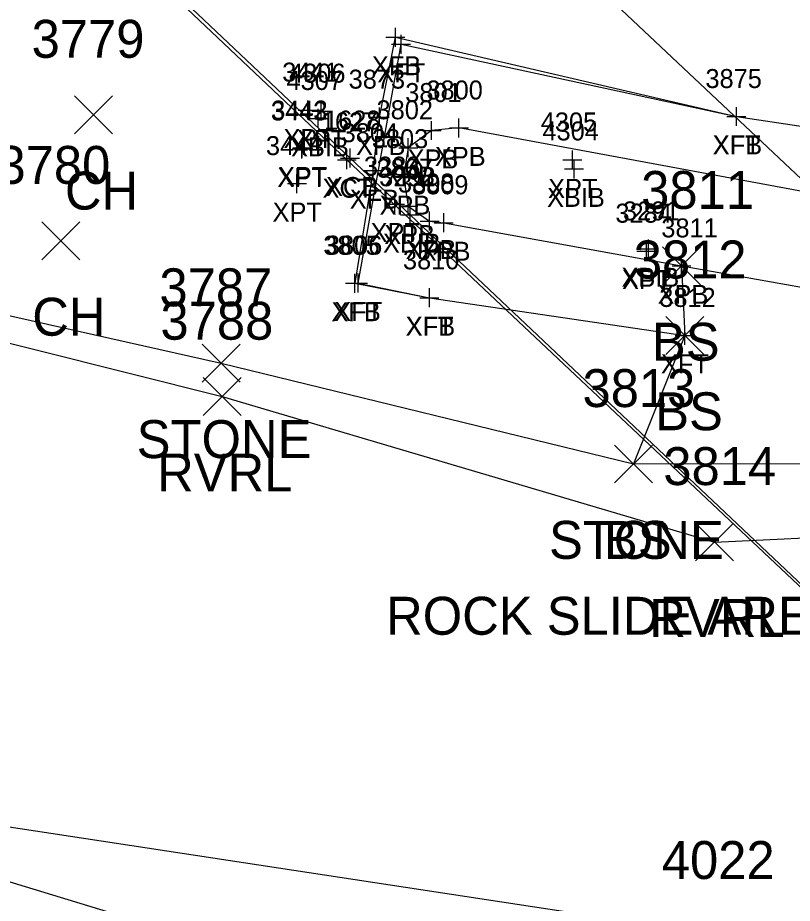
# Model space of a CAD drawing. Extents: x 1647574 to 1652703, y 212895 to 228670.
# Drawn here: x 1648950.84 to 1648991.67, y 227169.71 to 227216.38 of the extents above; entities that cross this region are included whole.
import ezdxf

# ---------------------------------------------------------------- set-up
doc = ezdxf.new("R2010")
doc.units = 0
for name, color, linetype in [('B_A', 7, 'Continuous'), ('B_I', 7, 'Continuous'), ('B_TIC', 7, 'Continuous'), ('BDC', 7, 'Continuous'), ('BELB', 7, 'Continuous'), ('BFT', 7, 'Continuous'), ('BSUBM', 7, 'Continuous'), ('L_A', 7, 'Continuous'), ('L_C', 7, 'Continuous'), ('L_I', 7, 'Continuous'), ('L_TIC', 7, 'Continuous'), ('LASF', 7, 'Continuous'), ('LAWE', 7, 'Continuous'), ('LELB', 7, 'Continuous')]:
    doc.layers.add(name, color=color, linetype=linetype)

msp = doc.modelspace()

# ---------------------------------------------------------------- linework, layer by layer
at = {"layer": 'B_TIC'}
for p, q in [((1648970.75, 227215.354), (1648970.825, 227215.354)), ((1648971.054, 227214.981), (1648971.129, 227214.981)), ((1648966.13, 227211.517), (1648966.205, 227211.517)), ((1648966.678, 227211.075), (1648966.754, 227211.075)), ((1648966.843, 227211.462), (1648966.918, 227211.462)), ((1648969.916, 227211.146), (1648969.991, 227211.146)), ((1648988.726, 227211.177), (1648988.801, 227211.177)), ((1648988.726, 227211.177), (1648988.801, 227211.177)), ((1648974.097, 227210.575), (1648974.172, 227210.575)), ((1648972.655, 227210.44), (1648972.73, 227210.44)), ((1648965.814, 227209.469), (1648965.889, 227209.469)), ((1648965.838, 227209.518), (1648965.913, 227209.518)), ((1648971.426, 227209.531), (1648971.502, 227209.531)), ((1648968.19, 227208.898), (1648968.265, 227208.898)), ((1648968.358, 227208.988), (1648968.434, 227208.988)), ((1648980.081, 227208.89), (1648980.157, 227208.89)), ((1648969.587, 227208.323), (1648969.662, 227208.323)), ((1648969.587, 227208.323), (1648969.662, 227208.323)), ((1648980.172, 227208.415), (1648980.248, 227208.415)), ((1648971.178, 227208.007), (1648971.254, 227208.007)), ((1648965.555, 227207.643), (1648965.631, 227207.643)), ((1648970.722, 227206.561), (1648970.798, 227206.561)), ((1648971.428, 227206.454), (1648971.503, 227206.454)), ((1648971.523, 227206.001), (1648971.599, 227206.001)), ((1648972.555, 227205.669), (1648972.63, 227205.669)), ((1648973.298, 227205.577), (1648973.374, 227205.577)), ((1648983.98, 227204.082), (1648984.055, 227204.082)), ((1648984.095, 227204.202), (1648984.17, 227204.202)), ((1648985.833, 227203.305), (1648985.909, 227203.305)), ((1648968.618, 227202.39), (1648968.694, 227202.39)), ((1648968.782, 227202.399), (1648968.858, 227202.399)), ((1648968.782, 227202.399), (1648968.858, 227202.399)), ((1648972.54, 227201.623), (1648972.615, 227201.623)), ((1648972.54, 227201.623), (1648972.615, 227201.623)), ((1648986.007, 227199.641), (1648986.082, 227199.641))]:
    msp.add_line(p, q, dxfattribs=at)
for points in [[(1648970.746, 227214.854), (1648970.746, 227215.854)], [(1648970.246, 227215.354), (1648971.246, 227215.354)], [(1648971.05, 227214.481), (1648971.05, 227215.481)], [(1648970.55, 227214.981), (1648971.55, 227214.981)], [(1648966.126, 227211.017), (1648966.126, 227212.017)], [(1648965.626, 227211.517), (1648966.626, 227211.517)], [(1648966.675, 227210.575), (1648966.675, 227211.575)], [(1648966.839, 227210.962), (1648966.839, 227211.962)], [(1648969.912, 227210.646), (1648969.912, 227211.646)], [(1648988.722, 227210.677), (1648988.722, 227211.677)], [(1648988.722, 227210.677), (1648988.722, 227211.677)], [(1648966.175, 227211.075), (1648967.175, 227211.075)], [(1648966.339, 227211.462), (1648967.339, 227211.462)], [(1648969.412, 227211.146), (1648970.412, 227211.146)], [(1648974.093, 227210.075), (1648974.093, 227211.075)], [(1648988.222, 227211.177), (1648989.222, 227211.177)], [(1648988.222, 227211.177), (1648989.222, 227211.177)], [(1648972.651, 227209.94), (1648972.651, 227210.94)], [(1648973.593, 227210.575), (1648974.593, 227210.575)], [(1648972.151, 227210.44), (1648973.151, 227210.44)], [(1648965.81, 227208.969), (1648965.81, 227209.969)], [(1648965.834, 227209.018), (1648965.834, 227210.018)], [(1648971.423, 227209.031), (1648971.423, 227210.031)], [(1648965.31, 227209.469), (1648966.31, 227209.469)], [(1648965.334, 227209.518), (1648966.334, 227209.518)], [(1648968.186, 227208.398), (1648968.186, 227209.398)], [(1648968.355, 227208.488), (1648968.355, 227209.488)], [(1648970.923, 227209.531), (1648971.923, 227209.531)], [(1648980.078, 227208.39), (1648980.078, 227209.39)], [(1648967.686, 227208.898), (1648968.686, 227208.898)], [(1648967.855, 227208.988), (1648968.855, 227208.988)], [(1648969.583, 227207.823), (1648969.583, 227208.823)], [(1648969.583, 227207.823), (1648969.583, 227208.823)], [(1648979.578, 227208.89), (1648980.578, 227208.89)], [(1648980.169, 227207.915), (1648980.169, 227208.915)], [(1648969.083, 227208.323), (1648970.083, 227208.323)], [(1648969.083, 227208.323), (1648970.083, 227208.323)], [(1648971.175, 227207.507), (1648971.175, 227208.507)], [(1648979.669, 227208.415), (1648980.669, 227208.415)], [(1648965.552, 227207.143), (1648965.552, 227208.143)], [(1648970.675, 227208.007), (1648971.675, 227208.007)], [(1648965.052, 227207.643), (1648966.052, 227207.643)], [(1648970.719, 227206.061), (1648970.719, 227207.061)], [(1648971.424, 227205.954), (1648971.424, 227206.954)], [(1648970.219, 227206.561), (1648971.219, 227206.561)], [(1648970.924, 227206.454), (1648971.924, 227206.454)], [(1648971.52, 227205.501), (1648971.52, 227206.501)], [(1648971.02, 227206.001), (1648972.02, 227206.001)], [(1648972.551, 227205.169), (1648972.551, 227206.169)], [(1648973.295, 227205.077), (1648973.295, 227206.077)], [(1648972.051, 227205.669), (1648973.051, 227205.669)], [(1648972.795, 227205.577), (1648973.795, 227205.577)], [(1648983.976, 227203.582), (1648983.976, 227204.582)], [(1648984.091, 227203.702), (1648984.091, 227204.702)], [(1648983.476, 227204.082), (1648984.476, 227204.082)], [(1648983.591, 227204.202), (1648984.591, 227204.202)], [(1648985.83, 227202.805), (1648985.83, 227203.805)], [(1648985.33, 227203.305), (1648986.33, 227203.305)], [(1648968.615, 227201.89), (1648968.615, 227202.89)], [(1648968.779, 227201.899), (1648968.779, 227202.899)], [(1648968.779, 227201.899), (1648968.779, 227202.899)], [(1648968.115, 227202.39), (1648969.115, 227202.39)], [(1648968.279, 227202.399), (1648969.279, 227202.399)], [(1648968.279, 227202.399), (1648969.279, 227202.399)], [(1648972.536, 227201.123), (1648972.536, 227202.123)], [(1648972.536, 227201.123), (1648972.536, 227202.123)], [(1648972.036, 227201.623), (1648973.036, 227201.623)], [(1648972.036, 227201.623), (1648973.036, 227201.623)], [(1648986.003, 227199.141), (1648986.003, 227200.141)], [(1648985.503, 227199.641), (1648986.503, 227199.641)]]:
    msp.add_lwpolyline(points, dxfattribs=at)
at = {"layer": 'BDC'}
for points in [[(1649190.777, 226999.084), (1649140.468, 227046.558), (1649090.33, 227093.733), (1649025.71, 227154.751), (1648968.186, 227208.898), (1648910.789, 227263.155), (1648860.431, 227310.794), (1648808.664, 227359.741)], [(1649190.944, 226999.114), (1649140.59, 227046.719), (1649090.397, 227093.864), (1649025.741, 227154.791), (1648968.355, 227208.988), (1648910.836, 227263.351), (1648860.59, 227310.809), (1648808.767, 227359.651)]]:
    msp.add_lwpolyline(points, dxfattribs=at)
at = {"layer": 'BELB'}
msp.add_lwpolyline([(1649218.046, 226994.506), (1649168.124, 227041.655), (1649117.675, 227088.79), (1649053.801, 227149.566), (1648996.598, 227203.697), (1648938.733, 227258.119), (1648889.571, 227305.276), (1648838.072, 227353.54)], dxfattribs=at)
at = {"layer": 'BFT'}
for points in [[(1648969.583, 227208.323), (1648969.912, 227211.146), (1648970.746, 227215.354), (1648988.722, 227211.177)], [(1648968.779, 227202.399), (1648971.05, 227214.981), (1648988.722, 227211.177), (1649022.914, 227206.066)], [(1648969.583, 227208.323), (1648968.615, 227202.39), (1648972.536, 227201.623)], [(1648968.779, 227202.399), (1648972.536, 227201.623), (1648986.003, 227199.641)]]:
    msp.add_lwpolyline(points, dxfattribs=at)
at = {"layer": 'BSUBM'}
msp.add_lwpolyline([(1648974.093, 227210.575), (1648972.651, 227210.44), (1648971.423, 227209.531), (1648971.175, 227208.007), (1648971.424, 227206.454), (1648972.551, 227205.669), (1648973.295, 227205.577), (1648985.83, 227203.305), (1648994.526, 227201.766), (1648998.617, 227201.072), (1649002.003, 227200.334), (1649005.371, 227199.79), (1649006.714, 227199.334), (1649014.364, 227197.781), (1649016.938, 227197.386), (1649018.515, 227197.402), (1649019.628, 227198.236), (1649020.065, 227199.413), (1649019.938, 227200.493), (1649019.383, 227201.576), (1649018, 227202.346), (1648995.997, 227206.525), (1648974.093, 227210.575)], dxfattribs=at)
at = {"layer": 'L_TIC'}
for points in [[(1648953.836, 227210.271), (1648955.836, 227212.271)], [(1648955.836, 227210.271), (1648953.836, 227212.271)], [(1648952.113, 227203.625), (1648954.113, 227205.625)], [(1648954.113, 227203.625), (1648952.113, 227205.625)], [(1648984.83, 227202.305), (1648986.83, 227204.305)], [(1648986.83, 227202.305), (1648984.83, 227204.305)], [(1648985.003, 227198.641), (1648987.003, 227200.641)], [(1648987.003, 227198.641), (1648985.003, 227200.641)], [(1648960.566, 227197.174), (1648962.566, 227199.174)], [(1648962.566, 227197.174), (1648960.566, 227199.174)], [(1648960.62, 227195.414), (1648962.62, 227197.414)], [(1648962.62, 227195.414), (1648960.62, 227197.414)], [(1648982.303, 227191.864), (1648984.303, 227193.864)], [(1648984.303, 227191.864), (1648982.303, 227193.864)], [(1648982.303, 227191.864), (1648984.303, 227193.864)], [(1648984.303, 227191.864), (1648982.303, 227193.864)], [(1648986.564, 227187.752), (1648988.564, 227189.752)], [(1648988.564, 227187.752), (1648986.564, 227189.752)]]:
    msp.add_lwpolyline(points, dxfattribs=at)
at = {"layer": 'LASF'}
for points in [[(1648499.797, 227390.788), (1648534.237, 227361.964), (1648564.139, 227335.998), (1648594.151, 227310.22), (1648628.599, 227293.401), (1648654.269, 227279.63), (1648686.156, 227265.624), (1648717.135, 227256.764), (1648740.627, 227248.949), (1648765.894, 227244.077), (1648814.223, 227231.854), (1648833.279, 227225.74), (1648856.547, 227221.689), (1648882.063, 227215.369), (1648909.355, 227210.97), (1648936.503, 227203.804), (1648961.566, 227198.174), (1648983.303, 227192.864), (1648997.705, 227192.889), (1649002.003, 227200.334)], [(1648591.009, 227270.343), (1648624.693, 227258.455), (1648664.933, 227242.862), (1648702.926, 227233.816), (1648737.154, 227219.4), (1648772.089, 227211.83), (1648798.883, 227202.714), (1648829.377, 227195.595), (1648870.643, 227189.301), (1648888.064, 227189.998), (1648910.238, 227184.26), (1648945.065, 227174.552), (1648988.129, 227167.991), (1649019.013, 227162.278), (1649093.93, 227148.389), (1649131.468, 227140.127), (1649155.823, 227137.226), (1649206.951, 227127.276), (1649258.232, 227116.863), (1649289.141, 227114.771), (1649313.58, 227109.451)]]:
    msp.add_lwpolyline(points, dxfattribs=at)
at = {"layer": 'LAWE'}
msp.add_lwpolyline([(1648882.174, 227213.58), (1648908.492, 227208.957), (1648937.017, 227202.591), (1648961.62, 227196.414), (1648987.564, 227188.752), (1648995.627, 227189.125), (1648999.847, 227187.562), (1649015.768, 227185.251), (1649058.819, 227180.733), (1649088.746, 227176.451), (1649126.054, 227169.003), (1649155.538, 227162.793), (1649190.065, 227156.482), (1649213.142, 227152.135), (1649245.722, 227144.443), (1649279.437, 227140.081), (1649297.816, 227135.47), (1649313.399, 227135.549)], dxfattribs=at)
at = {"layer": 'LELB'}
for points in [[(1648597.273, 227264.486), (1648633.73, 227250.634), (1648664.389, 227240.318), (1648701.872, 227228.729), (1648735.461, 227216.545), (1648770.192, 227206.754), (1648796.996, 227200.241), (1648829.006, 227192.504), (1648869.112, 227184.885), (1648887.117, 227184.175), (1648909.076, 227180.513), (1648944.404, 227172.664), (1648985.415, 227160.185), (1649015.972, 227155.751), (1649030.56, 227151.792), (1649075.874, 227142.707), (1649094.964, 227142.334), (1649128.793, 227137.178), (1649163.599, 227126.992), (1649206.12, 227120.023), (1649254.696, 227110.714), (1649288.497, 227104.847), (1649312.044, 227099.384)], [(1648985.83, 227203.305), (1648986.003, 227199.641), (1648983.303, 227192.864)]]:
    msp.add_lwpolyline(points, dxfattribs=at)

# ---------------------------------------------------------------- texts
at = {"layer": 'B_A'}
for s, p in [('XFB', (1648969.506, 227213.354)), ('XFT', (1648969.794, 227212.981)), ('XPT', (1648964.847, 227209.517)), ('XPT', (1648965.56, 227209.462)), ('XFB', (1648968.672, 227209.146)), ('XFT', (1648987.466, 227209.177)), ('XFB', (1648987.482, 227209.177)), ('XBIB', (1648965.246, 227209.075)), ('XPB', (1648971.388, 227208.44)), ('XPB', (1648972.829, 227208.575)), ('XPT', (1648964.531, 227207.469)), ('XPT', (1648964.555, 227207.518)), ('XPB', (1648970.159, 227207.531)), ('XCT', (1648966.907, 227206.898)), ('XCB', (1648967.091, 227206.988)), ('XPT', (1648978.798, 227206.89)), ('XFB', (1648968.343, 227206.323)), ('XFB', (1648968.343, 227206.323)), ('XBIB', (1648978.74, 227206.415)), ('XPB', (1648969.911, 227206.007)), ('XPT', (1648964.272, 227205.643)), ('XPT', (1648969.44, 227204.561)), ('XPB', (1648970.161, 227204.454)), ('XBIB', (1648970.091, 227204.001)), ('XPB', (1648971.288, 227203.669)), ('XPB', (1648972.031, 227203.577)), ('XBIB', (1648982.662, 227202.202)), ('XPT', (1648982.697, 227202.082)), ('XPB', (1648984.566, 227201.305)), ('XFB', (1648967.375, 227200.39)), ('XFT', (1648967.523, 227200.399)), ('XFT', (1648967.523, 227200.399)), ('XFT', (1648971.28, 227199.623)), ('XFB', (1648971.296, 227199.623)), ('XFT', (1648984.747, 227197.641))]:
    msp.add_text(s, height=1, dxfattribs=at).set_placement(p)
at = {"layer": 'B_I'}
for s, p in [('3441', (1648964.78, 227213.017)), ('4306', (1648965.142, 227212.962)), ('4307', (1648965.005, 227212.575)), ('3873', (1648968.282, 227212.646)), ('3875', (1648987.092, 227212.677)), ('3875', (1648987.092, 227212.677)), ('3801', (1648971.266, 227211.94)), ('3800', (1648972.381, 227212.075)), ('3443', (1648964.18, 227210.969)), ('3442', (1648964.204, 227211.018)), ('3802', (1648969.754, 227211.031)), ('1627', (1648966.816, 227210.398)), ('1628', (1648966.985, 227210.488)), ('4305', (1648978.409, 227210.39)), ('3804', (1648967.914, 227209.823)), ('3804', (1648967.914, 227209.823)), ('4304', (1648978.499, 227209.915)), ('3444', (1648963.922, 227209.143)), ('3803', (1648969.505, 227209.507)), ('3283', (1648969.089, 227208.061)), ('3807', (1648969.755, 227207.954)), ('3292', (1648969.89, 227207.501)), ('3808', (1648970.882, 227207.169)), ('3809', (1648971.622, 227207.077)), ('3284', (1648982.346, 227205.582)), ('3291', (1648982.745, 227205.702)), ('3811', (1648984.767, 227204.805)), ('3805', (1648966.945, 227203.89)), ('3806', (1648967.082, 227203.899)), ('3806', (1648967.082, 227203.899)), ('3810', (1648971.146, 227203.123)), ('3810', (1648971.146, 227203.123)), ('3812', (1648984.657, 227201.141))]:
    msp.add_text(s, height=1, dxfattribs=at).set_placement(p)
at = {"layer": 'L_A'}
for s, p in [('CH', (1648953.325, 227206.271)), ('CH', (1648951.602, 227199.625)), ('BS', (1648984.271, 227198.305)), ('BS', (1648984.444, 227194.641)), ('STONE', (1648957.109, 227193.174)), ('RVRL', (1648958.187, 227191.414)), ('STONE', (1648978.846, 227187.864)), ('BS', (1648981.744, 227187.864)), ('RVRL', (1648984.131, 227183.752))]:
    msp.add_text(s, height=2, dxfattribs=at).set_placement(p)
at = {"layer": 'L_C'}
msp.add_text('ROCK SLIDE AREA', height=2, dxfattribs=at).set_placement((1648970.256, 227183.864))
at = {"layer": 'L_I'}
for s, p in [('3779', (1648951.569, 227214.271)), ('3780', (1648949.767, 227207.625)), ('3811', (1648983.704, 227206.305)), ('3812', (1648983.31, 227202.641)), ('3787', (1648958.306, 227201.174)), ('3788', (1648958.361, 227199.414)), ('3813', (1648980.61, 227195.864)), ('3813', (1648980.61, 227195.864)), ('3814', (1648984.871, 227191.752)), ('4022', (1648984.791, 227170.991))]:
    msp.add_text(s, height=2, dxfattribs=at).set_placement(p)

doc.saveas('drawing.dxf')
